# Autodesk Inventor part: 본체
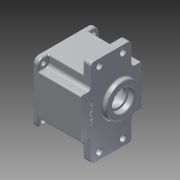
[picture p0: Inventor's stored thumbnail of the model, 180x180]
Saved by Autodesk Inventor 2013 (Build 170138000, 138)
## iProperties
Created: 2015-07
Part Number: 본체
Material: 알루미늄 6061
Document SubType Name: Modeling
Designer: user
Density: 2.71 g/cm^3
Mass: 702.244 g
Surface Area: 676.144 cm^2
Volume: 259.131 cm^3
Author: user
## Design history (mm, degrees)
sketch "스케치4"
  geometry: L1 (-45, 45)-(45, 45); L2 (45, 45)-(45, -45); L3 (45, -45)-(-45, -45); L4 (-45, -45)-(-45, 45); 3 further points
  constraints: 8 end point, 2 midpoint, 2 parallel, 1 horizontal, 1 horizontal alignment, 1 perpendicular, 1 vertical alignment
  dimensions: "d10" = 90 distance of L2.end L3.end; "d11" = 90 distance of L1.end L2.end
extrude "돌출3" new body sketch "스케치4" stored distance "d12" = 70; taper "d13" = 0 deg
sketch "스케치5"
  geometry: L1 (-45, 45)-(-45, -45) reference; L2 (-65, 30)-(65, 30); L3 (65, 30)-(65, -30); L4 (65, -30)-(-65, -30); L5 (-65, -30)-(-65, 30); 4 further points
  constraints: 8 end point, 3 midpoint, 2 parallel, 1 horizontal, 1 horizontal alignment, 1 perpendicular, 1 vertical alignment
  dimensions: "d14" = 130 distance of L3.end L4.end; "d15" = 60 distance of L2.end L3.end
extrude "돌출4" join sketch "스케치5" distance "d16" = 12; taper "d17" = 0 deg
sketch "스케치6"
  geometry: L1 (-45, -30)-(-45, -45) reference; L2 (-45, -45)-(45, -45) reference; L3 (45, -45)-(45, -30) reference; L4 (45, 30)-(45, 45) reference; L5 (45, 45)-(-45, 45) reference; L6 (-45, 45)-(-45, 30) reference; L7 (-45, -30)-(-65, -30) reference; L8 (45, 30)-(30, 30); L9 (30, 30)-(30, 45); L10 (30, 45)-(45, 45); L11 (45, 30)-(45, 45); L12 (45, -45)-(30, -45); L13 (30, -45)-(30, -30); L14 (30, -30)-(45, -30); L15 (45, -30)-(45, -45); L16 (-45, 30)-(-45, 45); L17 (-45, 45)-(-30, 45); L18 (-30, 45)-(-30, 30); L19 (-30, 30)-(-45, 30); L20 (-45, -45)-(-45, -30); L21 (-45, -30)-(-30, -30); L22 (-30, -30)-(-30, -45); L23 (-30, -45)-(-45, -45); 1 further point
  constraints: 32 end point, 5 collinear, 4 perpendicular, 4 point on line, 2 parallel
  dimensions: "d18" = 15 distance of L4.start L8.end; "d19" = 15 distance of L2.end L12.end; "d20" = 15 distance of L12.end L13.end; "d21" = 15 distance of L5.end L17.end; "d22" = 15 distance of L17.end L18.end; "d23" = 15 distance of L1.start L21.end; "d24" = 15 distance of L21.end L22.end
extrude "돌출5" cut sketch "스케치6" distance "d25" = 63; taper "d26" = 0 deg
sketch "스케치7"
  geometry: C1 r 40 at (0, 0); 1 further point
  constraints: 1 centre point, 1 coincident
  dimensions: "d27" = 80 diameter of C1
extrude "돌출6" cut sketch "스케치7" distance "d28" = 9; taper "d29" = 0 deg
sketch "스케치8"
  geometry: L1 (45, 30)-(45, -30) reference; L2 (45, -30)-(30, -30) reference; L3 (30, -30)-(30, -45) reference; L4 (30, -45)-(-30, -45) reference; L5 (-30, -45)-(-30, -30) reference; L6 (-30, -30)-(-45, -30) reference; L7 (-45, -30)-(-45, 30) reference; L8 (-45, 30)-(-30, 30) reference; L9 (-30, 30)-(-30, 45) reference; L10 (-30, 45)-(30, 45) reference; L11 (30, 45)-(30, 30) reference; L12 (30, 30)-(45, 30) reference; L13 (45, 30)-(45, -30) reference; L14 (45, -30)-(30, -30) reference; L15 (30, -30)-(30, -45) reference; L16 (30, -45)-(-30, -45) reference; L17 (-30, -45)-(-30, -30) reference; L18 (-30, -30)-(-45, -30) reference; L19 (-45, -30)-(-45, 30) reference; L20 (-45, 30)-(-30, 30) reference; L21 (-30, 30)-(-30, 45) reference; L22 (-30, 45)-(30, 45) reference; L23 (30, 45)-(30, 30) reference; L24 (30, 30)-(45, 30) reference; C1 r 40 at (0, 0) reference; C2 r 40 at (0, 0) reference; C3 r 39 at (0, 0)
  constraints: 1 centre point, 1 coincident
  dimensions: "d30" = 78 diameter of C3
extrude "돌출7" cut sketch "스케치8" distance "d31" = 52; taper "d32" = 0 deg
sketch "스케치9"
  geometry: L1 (30, 45)-(30, 30) reference; L2 (30, 30)-(65, 30) reference; L3 (65, 30)-(65, -30) reference; L4 (65, -30)-(30, -30) reference; L5 (30, -30)-(30, -45) reference; L6 (30, -45)-(-30, -45) reference; L7 (-30, -45)-(-30, -30) reference; L8 (-30, -30)-(-65, -30) reference; L9 (-65, -30)-(-65, 30) reference; L10 (-65, 30)-(-30, 30) reference; L11 (-30, 30)-(-30, 45) reference; L12 (-30, 45)-(30, 45) reference; L13 (0, 0)-(35, 0); L14 (0, 0)-(24.749, 24.749); C1 r 39 at (0, 0) reference; C2 r 4 at (24.749, 24.749); A1 r 39 centre (0, 0) between (32.777, 21.134) and (21.134, 32.777) reference; A2 r 35 centre (0, 0) between (35, 0) and (24.749, 24.749); A3 r 3.5 centre (29.836, 19.238) between (32.777, 21.134) and (27.412, 21.762); A4 r 3.5 centre (19.238, 29.836) between (21.762, 27.412) and (21.134, 32.777)
  constraints: 10 point on circle, 4 centre point, 4 end point, 4 tangent, 2 coincident, 1 parallel
  dimensions: "d33" = 70 diameter of A2; "d34" = 45 deg angle of L13 L14; "d36" = 8 diameter of C2; "d37" = 7 diameter of A3; "d38" = 7 diameter of A4
extrude "돌출8" join sketch "스케치9" distance "d39" = 52; taper "d40" = 0 deg
sketch "스케치10"
  geometry: L1 (30, 45)-(30, 30) reference; L2 (30, 30)-(65, 30) reference; L3 (65, 30)-(65, -30) reference; L4 (65, -30)-(30, -30) reference; L5 (30, -30)-(30, -45) reference; L6 (30, -45)-(-30, -45) reference; L7 (-30, -45)-(-30, -30) reference; L8 (-30, -30)-(-65, -30) reference; L9 (-65, -30)-(-65, 30) reference; L10 (-65, 30)-(-30, 30) reference; L11 (-30, 30)-(-30, 45) reference; L12 (-30, 45)-(30, 45) reference; L13 (0, 0)-(0, 11); L14 (0, 0)-(0, -20); C1 r 20.5 at (0, 11); C2 r 14 at (0, -20); A1 r 4 centre (24.749, 24.749) between (21.763, 27.411) and (27.411, 21.763) reference; A2 r 35 centre (0, 0) between (21.763, 27.411) and (21.762, 27.412) reference; A3 r 3.5 centre (19.238, 29.836) between (21.762, 27.412) and (21.134, 32.777) reference; A4 r 39 centre (0, 0) between (21.134, 32.777) and (-21.134, 32.777) reference; A5 r 3.5 centre (-19.238, 29.836) between (-21.134, 32.777) and (-21.762, 27.412) reference; A6 r 35 centre (0, 0) between (-21.762, 27.412) and (-21.763, 27.411) reference; A7 r 4 centre (-24.749, 24.749) between (-27.411, 21.763) and (-21.763, 27.411) reference; A8 r 35 centre (0, 0) between (-27.411, 21.763) and (-27.412, 21.762) reference; A9 r 3.5 centre (-29.836, 19.238) between (-27.412, 21.762) and (-32.777, 21.134) reference; A10 r 39 centre (0, 0) between (-32.777, 21.134) and (-32.777, -21.134) reference; A11 r 3.5 centre (-29.836, -19.238) between (-32.777, -21.134) and (-27.412, -21.762) reference; A12 r 35 centre (0, 0) between (-27.412, -21.762) and (-27.411, -21.763) reference; A13 r 4 centre (-24.749, -24.749) between (-21.763, -27.411) and (-27.411, -21.763) reference; A14 r 35 centre (0, 0) between (-21.763, -27.411) and (-21.762, -27.412) reference; A15 r 3.5 centre (-19.238, -29.836) between (-21.762, -27.412) and (-21.134, -32.777) reference; A16 r 39 centre (0, 0) between (-21.134, -32.777) and (21.134, -32.777) reference; A17 r 3.5 centre (19.238, -29.836) between (21.134, -32.777) and (21.762, -27.412) reference; A18 r 35 centre (0, 0) between (21.762, -27.412) and (21.763, -27.411) reference; A19 r 4 centre (24.749, -24.749) between (27.411, -21.763) and (21.763, -27.411) reference; A20 r 35 centre (0, 0) between (27.411, -21.763) and (27.412, -21.762) reference; A21 r 3.5 centre (29.836, -19.238) between (27.412, -21.762) and (32.777, -21.134) reference; A22 r 39 centre (0, 0) between (32.777, -21.134) and (32.777, 21.134) reference; A23 r 3.5 centre (29.836, 19.238) between (32.777, 21.134) and (27.412, 21.762) reference; A24 r 35 centre (0, 0) between (27.412, 21.762) and (27.411, 21.763) reference
  constraints: 4 end point, 2 centre point, 2 coincident, 1 collinear, 1 perpendicular
  dimensions: "d44" = 11 distance of L13.start L13.end; "d45" = 41 diameter of C1; "d46" = 20 distance of L13.start L14.end; "d47" = 28 diameter of C2
extrude "돌출9" join sketch "스케치10" distance "d48" = 7; taper "d49" = 0 deg
sketch "스케치11"
  geometry: C1 r 11 at (0, -20); A1 r 14 centre (0, -20) between (-7.402, -8.117) and (7.402, -8.117) reference; 1 further point
  constraints: 1 centre point, 1 coincident
  dimensions: "d50" = 22 diameter of C1
extrude "돌출10" cut sketch "스케치11" distance "d51" = 7; taper "d52" = 0 deg
sketch "스케치12"
  geometry: C1 r 11 at (0, 0) reference; C2 r 9.5 at (0, 0); 1 further point
  constraints: 1 centre point, 1 coincident
  dimensions: "d53" = 19 diameter of C2
extrude "돌출11" cut sketch "스케치12" distance "d54" = 1; taper "d55" = 0 deg
sketch "스케치13"
  geometry: C1 r 17.5 at (0, 11); A1 r 20.5 centre (0, 11) between (7.402, -8.117) and (-7.402, -8.117) reference; 1 further point
  constraints: 1 centre point, 1 coincident
  dimensions: "d56" = 35 diameter of C1
extrude "돌출12" cut sketch "스케치13" distance "d57" = 10; taper "d58" = 0 deg
sketch "스케치14"
  geometry: L1 (65, 30)-(30, 30) reference; L2 (0, 0)-(0, 11); C1 r 25 at (0, 11)
  constraints: 2 end point, 1 centre point, 1 coincident, 1 perpendicular
  dimensions: "d59" = 11 distance of L2.start L2.end; "d60" = 50 diameter of C1
extrude "돌출13" join sketch "스케치14" distance "d61" = 7; taper "d62" = 0 deg
sketch "스케치15"
  geometry: C1 r 17.5 at (0, 0) reference; C2 r 12.5 at (0, 0); 1 further point
  constraints: 1 centre point, 1 coincident
  dimensions: "d63" = 25 diameter of C2
extrude "돌출14" cut sketch "스케치15" distance "d64" = 5; taper "d65" = 0 deg
sketch "스케치16"
  geometry: C1 r 12.5 at (0, 0) reference; C2 r 16 at (0, 0); 1 further point
  constraints: 1 centre point, 1 coincident
  dimensions: "d66" = 32 diameter of C2
extrude "돌출15" cut sketch "스케치16" distance "d67" = 8; taper "d68" = 0 deg
fillet "모깎기1" dims "d69" = 0.3
fillet "모깎기2" dims "d70" = 0.3
chamfer "모따기1" distance "d71" = 1; stored, may be unused: second distance "d72" = 2, angle "d73" = 45 deg
fillet "모깎기3" dims "d74" = 3
fillet "모깎기4" dims "d75" = 2
fillet "모깎기5" dims "d76" = 2
fillet "모깎기6" dims "d77" = 2
fillet "모깎기7" dims "d78" = 2
fillet "모깎기8" dims "d79" = 8
sketch "스케치17"
  geometry: A1 r 8 centre (37, -37) between (37, -45) and (45, -37) reference; A2 r 8 centre (37, 37) between (45, 37) and (37, 45) reference; A3 r 8 centre (-37, 37) between (-37, 45) and (-45, 37) reference; A4 r 8 centre (-37, -37) between (-45, -37) and (-37, -45) reference
hole "구멍1" sketch "스케치17" at (-37, 37), (37, 37), (37, -37), (-37, -37) diameter "d80" = 7; stored, may be unused: countersink angle "d84" = 90 deg, drill point angle "d86" = 118 deg; dims "d81" = 6, "d82" = 4, "d83" = 2, "d85" = 10
sketch "스케치18"
  geometry: A1 r 4 centre (24.749, -24.749) between (27.411, -21.763) and (21.763, -27.411) reference; A2 r 4 centre (-24.749, -24.749) between (-21.763, -27.411) and (-27.411, -21.763) reference; A3 r 4 centre (-24.749, 24.749) between (-27.411, 21.763) and (-21.763, 27.411) reference; A4 r 4 centre (24.749, 24.749) between (21.763, 27.411) and (27.411, 21.763) reference
hole "구멍2" sketch "스케치18" at (24.749, 24.749), (24.749, -24.749), (-24.749, 24.749), (-24.749, -24.749) diameter "d87" = 3.459; stored, may be unused: countersink angle "d91" = 90 deg, drill point angle "d93" = 118 deg; dims "d88" = 12, "d89" = 4, "d90" = 2, "d92" = 15
fillet "모깎기9" dims "d94" = 5
fillet "모깎기10" dims "d95" = 2
sketch "스케치19"
  geometry: L1 (65, 25)-(65, -25) reference; L2 (55, 17.5)-(55, -17.5); L3 (55, 0)-(-55, 0); L4 (0, 0)-(0, 22); C1 r 4.5 at (55, 17.5); C2 r 4.5 at (55, -17.5); C3 r 4.5 at (-55, 17.5); C4 r 4.5 at (-55, -17.5); 1 further point
  constraints: 6 end point, 4 centre point, 3 coincident, 2 midpoint, 2 perpendicular, 2 symmetric about line, 1 horizontal alignment, 1 parallel, 2 other
  dimensions: "d96" = 35 distance of L2.start L2.end; "d97" = 110 distance of L3.start L3.end; "d98" = 9 diameter of C1; "d99" = 9 diameter of C2
extrude "돌출16" cut sketch "스케치19" stored distance "d100" = 8; taper "d101" = 0 deg
fillet "모깎기11" dims "d102" = 2
fillet "모깎기12" dims "d103" = 2
fillet "모깎기13" dims "d104" = 2
sketch "스케치20"
  geometry: L1 (-28, -45)-(28, -45) reference; L2 (-30, -30)-(-30, -43) reference; L3 (0, -45)-(0, -30); 3 further points
  constraints: 2 end point, 1 coincident, 1 midpoint, 1 parallel, 1 other
  dimensions: "d105" = 15 distance of L3.start L3.end
feature "엠보싱1" sketch "스케치20" dims "d106" = 0.5, "d107" = 0
fillet "모깎기14" dims "d108" = 5
node "솔리드2"
pattern_circular "원형 패턴1" dims angle "d42" = 360 deg
node "절단 모서리 투영1"
node "절단 모서리 투영2"
node "절단 모서리 투영3"
node "절단 모서리 투영4"
